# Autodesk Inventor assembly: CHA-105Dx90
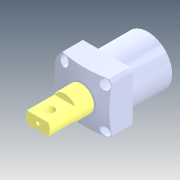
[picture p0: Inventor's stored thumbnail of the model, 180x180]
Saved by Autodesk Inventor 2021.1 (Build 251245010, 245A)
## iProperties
Created: 2018-07
Part Number: CHA-105Dx90
Description: STEP AP214
Document SubType Name: Assembly
Designer: user
Title: CHA-105Dx90.STEP
Revision Number: ÈÎºÎ
Sending System: SolidWorks 2016
Preprocessor: SwSTEP 2.0
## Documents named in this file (3)
- D:\Vault_2016\Projekty\Clamptek\Hydraulic\CHA\CHA\CHA-105\Inventor\CHA-105Dx90\CHA-105Dx90.iam
- D:\Vault_2016\Projekty\Clamptek\Hydraulic\CHA\CHA\CHA-105\Inventor\CHA-105Dx90\CHA-105BT.ipt
- D:\Vault_2016\Projekty\Clamptek\Hydraulic\CHA\CHA\CHA-105\Inventor\CHA-105Dx90\CHA-105D»îÈû¸Ë.ipt
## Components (2 placed, 2 different names)
1. CHA-105BT_1
2. CHA-105D»îÈû¸Ë_2
